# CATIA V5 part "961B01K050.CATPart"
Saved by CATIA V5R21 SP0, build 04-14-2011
Part number: 961B01K050
Bounding box of the stored display mesh (mm): x -18.1 to 18.1, y -25 to 25, z -10 to 4.5
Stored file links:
  C:\Users\ALI OZGUN\Desktop\alhan\961B01K050.CATPart
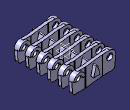
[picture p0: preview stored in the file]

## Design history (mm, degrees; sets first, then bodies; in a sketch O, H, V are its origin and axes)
Body1 (main body)
  Sketch1 on zx-plane, origin (0, 0, 0), H (-1, 0, 0), V (0, 0, 1)
    construction line L1 (-13.6, 0) -> (13.6, 0)
    point P1 (-13.6, 0)
    line L2 (-13.6, 4.5) -> (13.6, 4.5)
    line L3 (13.6, -4.5) -> (-13.6, -4.5)
    arc A1 centre (13.6, 0) radius 4.5 from (13.6, 4.5) to (13.6, -4.5) cw
    arc A2 centre (-13.6, 0) radius 4.5 from (-13.6, -4.5) to (-13.6, 4.5) cw
    distance L1 L2 = 4.5
    length L1 = 27.2
    distance P1 V = 13.6
    coincidence: P1 H
    horizontal: L1 H
    tangency: A1 L2, A2 L2, A1 L3, A2 L3
  Sketch2 on zx-plane, origin (0, 0, 0), H (-1, 0, 0), V (0, 0, 1)
    point P1 (-2.5, -4.5)
    line L1 (-2.5, -4.5) -> (-0.4806, 2.5379)
    point P2 (0, 4.2129)
    line L2 (0.4806, 2.5379) -> (2.5, -4.5)
    point P3 (2.5, -4.5)
    line L3 (2.5, -4.5) -> (-2.5, -4.5)
    arc A1 centre (0, 2.4) radius 0.5 from (-0.4806, 2.5379) to (0.4806, 2.5379) cw
    distance P3 P1 = 5
    distance L3 H = 4.5
    radius A1 = 0.5
    distance A1 L3 = 7.4
    horizontal: L3 H
    coincidence: L1 P2, L2 P2
    tangency: A1 L1, A1 L2
    symmetry: L1 L2 V
  Pad1: profile Sketch2, direction (0, 1, 0), length 25, mirrored extent
  Body2
    Pad2: profile Sketch8, direction (0, 0, 1), length 25, mirrored extent
    Pocket1: profile Sketch1, direction (0, -1, 0), length 25, outer side
    Fillet1: radius 5, on edge [face of Pad2 from Sketch8.L3 | face of Pad2 from Sketch8.L2]; edge [face of Pad2 from Sketch8.L8 | face of Pad2 from Sketch8.L7]; edge [face of Pad2 from Sketch8.L7 | face of Pad2 from Sketch8.L4]; edge [face of Pad2 from Sketch8.L2 | face of Pad2 from Sketch8.L1]
    RectPattern1: of the body so far, direction 1 instances 6, spacing 8.52, along yz-plane
    Sketch3 on face of Pad2 from Sketch8.L1, origin (0, -23.3, 0), H (1, 0, 0), V (0, 0, 1)
      arc A1 centre (-13.6, 0) radius 4.5 from (-9.1, 0) to (-18.1, 0) ccw
      line L1 (-9.2, 0) -> (-11.15, 0)
      arc A2 centre (-13.6, 0) radius 2.45 from (-11.15, 0) to (-16.05, 0) ccw
      reference projected arc E1 centre (-13.6, 0) radius 4.5 from (-13.6, 4.5) to (-13.6, -4.5) ccw from edge [face of Pocket1 from Sketch1.A1 | face of Pad2 from Sketch8.L1]
      point P5 (-16.05, 0)
      line L2 (-16.05, 0) -> (-18.1, 0)
      radius A1 = 4.5
      radius A2 = 2.45
      horizontal: L1 H, L2 H
      coincidence: L1 H, L1 P5, L1 L2
      concentricity: A1 E1
    Pad3: profile Sketch3, direction (0, -1, 0), length 1.7
    RectPattern2: of Pad3, direction 1 instances 6, spacing 8.52, along axis of face of Pocket1 from Sketch1.A2
    Sketch4 on face of RectPattern1, origin (0, 23.3, 0), H (-1, 0, 0), V (0, 0, 1)
      arc A1 centre (-13.6, 0) radius 4.5 from (-18.1, 0) to (-9.1, 0) cw
      line L1 (-18.1, 0) -> (-16.05, 0)
      arc A2 centre (-13.6, 0) radius 2.45 from (-16.05, 0) to (-11.15, 0) cw
      line L2 (-11.15, 0) -> (-9.1, 0)
      reference projected arc E1 centre (-13.6, 0) radius 4.5 from (-13.6, 4.5) to (-13.6, -4.5) ccw from edge [face of RectPattern1 | face of RectPattern1]
      reference projected line E2 (-7.6525, 4.5) -> (-13.6, 4.5) from edge [face of RectPattern1 | face of RectPattern1]
      radius A2 = 2.45
      distance L2 H = 0
      concentricity: A1 E1, A2 A1
      coincidence: L1 L2
      tangency: A1 E2
    Pad4: profile Sketch4, direction (0, 1, 0), length 1.7, opposite side length 1
    RectPattern3: of Pad4, direction 1 instances 6, spacing 8.52, along axis of face of RectPattern1 reversed
    Sketch5 on zx-plane, origin (0, 0, 0), H (-1, 0, 0), V (0, 0, 1)
      circle A1 centre (-13.6, 0) radius 2.45
      point P1 (-13.6, 0)
      circle A2 centre (13.6, 0) radius 2.4
      point P2 (13.6, 0)
      reference projected arc E1 centre (-13.6, 0) radius 2.45 from (-11.15, 0) to (-16.05, 0) ccw from edge [face of Pad4 from Sketch4.A2 | end face of Pad4]
      reference projected arc E2 centre (13.6, 0) radius 4.5 from (13.6, -4.5) to (13.6, 4.5) ccw from edge [face of RectPattern1 | face of RectPattern2]
      radius A2 = 2.4
      radius A1 = 2.45
      coincidence: P1 H, P2 H
      concentricity: A1 E1, A2 E2
    Pocket2: profile Sketch5, direction (0, -1, 0), length 32.7, mirrored extent
  Add1: tool Body2
  Body3
    Pad5: profile Sketch7, direction (0, 0, -1), length 5.5, opposite side length 4.5
    Draft1: Angle 5, Neutral start face of Pad5, PullDir start face of Pad5, SupportToDraft (face of Pad5 from Sketch7.E2; face of Pad5 from Sketch7.E4)
    Fillet2: radius 2, on edge [face of Pad5 from Sketch7.E4 | end face of Pad5]; edge [face of Pad5 from Sketch7.E2 | end face of Pad5]
    Fillet3: radius 5, on edge [face of Pad5 from Sketch7.L1 | face of Pad5 from Sketch7.L2]; edge [face of Pad5 from Sketch7.L2 | face of Pad5 from Sketch7.L3]; edge [face of Pad5 from Sketch7.L4 | face of Pad5 from Sketch7.L5]; edge [face of Pad5 from Sketch7.L5 | face of Pad5 from Sketch7.L6]
    Sketch6 on zx-plane, origin (0, 0, 0), H (-1, 0, 0), V (0, 0, 1)
      circle A1 centre (-13.6, 0) radius 2.45
      point P1 (-13.6, 0)
      circle A2 centre (13.6, 0) radius 2.4
      point P2 (13.6, 0)
      reference projected arc E1 centre (-13.6, 0) radius 2.45 from (-11.15, 0) to (-16.05, 0) ccw from edge [face of Pad4 from Sketch4.A2 | end face of Pad4]
      reference projected arc E2 centre (13.6, 0) radius 4.5 from (13.6, -4.5) to (13.6, 4.5) ccw from edge [face of RectPattern1 | face of RectPattern2]
      radius A2 = 2.4
      radius A1 = 2.45
      coincidence: P1 H, P2 H
      concentricity: A1 E1, A2 E2
    Pocket3: profile Sketch6, direction (0, -1, 0), length 32.7, mirrored extent
    RectPattern4: of the body so far, direction 1 instances 6, spacing 8.52, along axis of face of RectPattern3
  Add2: tool Body3
  Sketch7 on face of Pad1, origin (0, 0, -4.5), H (1, 0, 0), V (0, -1, 0)
    line L1 (-18.1, 23.3) -> (-7.5, 23.3)
    line L2 (-7.5, 23.3) -> (7.5, 21.6)
    line L3 (7.5, 21.6) -> (18.1, 21.6)
    line L4 (18.1, 19.3) -> (7.3701, 19.3)
    line L5 (7.3701, 19.3) -> (-7.759, 21.0146)
    line L6 (-7.759, 21.0146) -> (-18.1, 21.0146)
    projected line E1 (18.1, 19.3) -> (18.1, 17.6) from edge [face of RectPattern3 | face of RectPattern3]
    projected line E2 (18.1, 21.6) -> (18.1, 19.3) from edge [face of RectPattern3 | face of RectPattern3]
    projected line E3 (-18.1, 23.3) -> (-18.1, 25) from edge [face of Pad3 from Sketch3.L2 | face of Pad3]
    projected line E4 (-18.1, 21.0146) -> (-18.1, 23.3) from edge [face of Pad3 from Sketch3.L2 | face of Pad3]
    reference intersected line E5 (7.5, 21.6) -> (20, 21.6) from face of Pad2 from Sketch8.L3
    reference intersected line E6 (20, 19.3) -> (7.3701, 19.3) from face of Pad2 from Sketch8.L4
    reference intersected line E7 (-7.5, 23.3) -> (7.5, 21.6) from face of Pad2 from Sketch8.L2
    reference intersected line E8 (7.3701, 19.3) -> (-7.759, 21.0146) from face of Pad2 from Sketch8.L7
    reference intersected line E9 (-7.759, 21.0146) -> (-19.0192, 21.0146) from face of Pad2 from Sketch8.L8
    reference intersected line E10 (-19.0192, 23.3) -> (-7.5, 23.3) from face of Pad2 from Sketch8.L1
    coincidence: L3 E5, L4 E6, L2 E7, L5 E8, L6 E9, L1 E10
  Sketch8 on xy-plane, origin (0, 0, 0), H (1, 0, 0), V (0, 1, 0)
    line L1 (-19.0192, -23.3) -> (-7.5, -23.3)
    point P1 (-7.5, -23.3)
    line L2 (-7.5, -23.3) -> (7.5, -21.6)
    point P2 (7.5, -21.6)
    line L3 (7.5, -21.6) -> (20, -21.6)
    point P3 (20, -21.6)
    line L4 (7.3701, -19.3) -> (20, -19.3)
    point P4 (7.5, -19.3)
    construction line L5 (7.5, -21.6) -> (7.5, -19.3)
    construction line L6 (20, -21.6) -> (20, -19.3)
    line L7 (-7.759, -21.0146) -> (7.3701, -19.3)
    point P6 (-7.759, -21.0146)
    line L8 (-19.0192, -21.0146) -> (-7.759, -21.0146)
    line L9 (20, -19.3) -> (20, -21.6)
    line L10 (-19.0192, -21.0146) -> (-19.0192, -23.3)
    reference projected line E2 (-2.5, -25) -> (-0.4806, -25) from edge [start face of Pad1 | face of Pad1 from Sketch2.L2]
    distance P1 P2 H = 15
    distance L1 L3 = 1.7
    distance P1 V = 7.5
    distance P2 P3 = 12.5
    distance L3 L4 = 2.3
    distance L1 E2 = 1.7
    distance L10 L9 = 39.0192
    distance L8 L1 = 2.2854
    distance L7 L2 = 2.3
    horizontal: L1 H, L3 H
    perpendicularity: L5 L3, L5 L4, L6 L3, L6 L4
    coincidence: L8 P6, P4 L4, P6 L7
    vertical: L9 V, L10 V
